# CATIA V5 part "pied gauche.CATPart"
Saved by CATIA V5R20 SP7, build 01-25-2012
Part number: pied gauche bati
Bounding box of the stored display mesh (mm): x -30.69 to -6.692, y 42.178 to 67.258, z 66.692 to 91.024
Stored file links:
  F:\Travaux\Modélisations\CFAO_2011\CFAO_2011_MMS\CFAO_2011_MMS_DONE\CFAO_2011_MMS_jboiteux\Catia\pied gauche.CATPart
  U:\finthinkmotion\stepper.CATProduct
  F:\Travaux\Modélisations\CFAO_2011\CFAO_2011_MMS\CFAO_2011_MMS_DONE\CFAO_2011_MMS_jboiteux\Catia\bati.CATPart
  F:\Travaux\Modélisations\CFAO_2011\CFAO_2011_MMS\CFAO_2011_MMS_DONE\CFAO_2011_MMS_jboiteux\Catia\Part1.CATPart
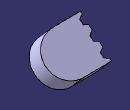
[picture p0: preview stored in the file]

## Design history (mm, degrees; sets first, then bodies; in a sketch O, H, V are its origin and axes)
Parameters
  rayontube = 9 mm {= External.royontubebati}
External parameters (linked from other documents)
  External.royontubebati = 9 mm
Set1
  DatumSurface1: linked copy from another document
  Point1: linked copy from another document
  Line1: linked copy from another document
  Line2: linked copy from another document
  DatumCurve1: linked copy from another document
Body1 (main body)
  Sketch1 on face of DatumSurface1, origin (0, 61.6478, 69.3538), H (-1, 0, 0), V (0, -0.7474, 0.6644)
    arc A1 centre (17.69, 11.4935) radius 11 from (17.69, 22.4935) to (17.69, 0.4935) ccw
    point P1 (17.69, 11.4935)
    point P2 (17.69, 22.4935)
    point P3 (17.69, 0.4935)
    reference projected point E1 (17.69, 11.4935) from Point1
    reference projected line E2 (17.69, 67.1007) -> (17.69, 13.2873) from Line1
    reference projected line E3 (17.69, 29.4313) -> (17.69, -42.32) from Line2
    point P4 (17.69, 22.4935)
    line L1 (17.69, 22.4935) -> (30.69, 22.4935)
    point P5 (30.69, 22.4935)
    point P6 (30.69, 22.4935)
    line L2 (30.69, 22.4935) -> (30.69, 21.2713)
    line L3 (30.69, 21.2713) -> (28.69, 20.049)
    point P8 (28.69, 20.049)
    line L4 (28.69, 20.049) -> (28.69, 17.6046)
    line L5 (28.69, 17.6046) -> (30.69, 16.7157)
    point P10 (30.69, 16.7157)
    line L6 (30.69, 16.7157) -> (30.69, 14.2713)
    line L7 (30.69, 14.2713) -> (28.69, 12.7157)
    line L8 (28.69, 12.7157) -> (28.69, 10.2713)
    point P13 (28.69, 10.2713)
    line L9 (28.69, 10.2713) -> (30.69, 9.049)
    point P14 (30.69, 9.049)
    line L10 (30.69, 9.049) -> (30.69, 6.6046)
    point P15 (30.69, 6.6046)
    line L11 (30.69, 6.6046) -> (28.69, 5.3824)
    point P16 (28.69, 5.3824)
    line L12 (28.69, 5.3824) -> (28.69, 2.9379)
    point P17 (28.69, 2.9379)
    line L13 (28.69, 2.9379) -> (30.69, 1.7157)
    line L14 (30.69, 1.7157) -> (30.69, 0.4935)
    line L15 (30.69, 0.4935) -> (17.69, 0.4935)
    point P20 (17.69, 0.4935)
    reference projected point E4 (17.69, 11.4935) from Point1
    projected circle E5 centre (17.69, 11.4935) radius 7 from edge of DatumCurve1
    radius A1 = 11 {= rayontube +2mm}
    length L2 = 1.2222 {= (rayontube +2mm)/9}
    length L4 = 2.4444 {= (rayontube +2mm)/4.5}
    length L6 = 2.4444 {= (rayontube+2mm)/4.5}
    length L8 = 2.4444 {= (rayontube+2mm)/4.5}
    length L10 = 2.4444 {= (rayontube+2mm)/4.5}
    length L12 = 2.4444 {= (rayontube+2mm)/4.5}
    length L14 = 1.2222 {= (rayontube+2mm)/9}
    distance P17 L15 = 2.4444 {= (rayontube+2mm)*4/18}
    distance P15 L15 = 6.1111 {= (rayontube+2mm)*10/18}
    distance P13 L15 = 9.7778 {= (rayontube+2mm)*16/18}
    distance L4 L2 = 2
    distance L8 E4 = 11 {= rayontube +2mm}
    distance L8 L10 = 2
    distance L12 L14 = 2
    distance P8 L1 = 2.4444 {= (rayontube+2mm)/4.5}
    coincidence: E1 P1, E2 P2, E3 P3, P4 A1, P10 L2, L5 P2, P14 L6, P16 L8, P20 P3, P6 P5, P2 P4
    tangency: L1 A1
    vertical: L2 V, L6 V, L10 V, L14 V
    horizontal: L15 H
  Pad1: profile Sketch1, direction (0, -0.6644, -0.7474), length 4
  Sketch2 on start face of Pad1, origin (0, 61.6478, 69.3538), H (-1, 0, 0), V (0, -0.7474, 0.6644)
    projected arc E1 centre (17.69, 11.4935) radius 11 from (17.69, 22.4935) to (17.69, 0.4935) ccw from edge [face of Pad1 from Sketch1.A1 | start face of Pad1]
    projected line E2 (17.69, 0.4935) -> (30.69, 0.4935) from edge [face of Pad1 from Sketch1.L15 | start face of Pad1]
    projected line E3 (30.69, 0.4935) -> (30.69, 1.7157) from edge [face of Pad1 from Sketch1.L14 | start face of Pad1]
    projected line E4 (30.69, 1.7157) -> (28.69, 2.9379) from edge [face of Pad1 from Sketch1.L13 | start face of Pad1]
    projected line E5 (28.69, 2.9379) -> (28.69, 5.3824) from edge [face of Pad1 from Sketch1.L12 | start face of Pad1]
    projected line E6 (28.69, 5.3824) -> (30.69, 6.6046) from edge [face of Pad1 from Sketch1.L11 | start face of Pad1]
    projected line E7 (30.69, 6.6046) -> (30.69, 9.049) from edge [face of Pad1 from Sketch1.L10 | start face of Pad1]
    projected line E8 (30.69, 9.049) -> (28.69, 10.2713) from edge [face of Pad1 from Sketch1.L9 | start face of Pad1]
    projected line E9 (28.69, 10.2713) -> (28.69, 12.7157) from edge [face of Pad1 from Sketch1.L8 | start face of Pad1]
    projected line E10 (28.69, 12.7157) -> (30.69, 14.2713) from edge [face of Pad1 from Sketch1.L7 | start face of Pad1]
    projected line E11 (30.69, 14.2713) -> (30.69, 16.7157) from edge [face of Pad1 from Sketch1.L6 | start face of Pad1]
    projected line E12 (30.69, 16.7157) -> (28.69, 17.6046) from edge [face of Pad1 from Sketch1.L5 | start face of Pad1]
    projected line E13 (28.69, 17.6046) -> (28.69, 20.049) from edge [face of Pad1 from Sketch1.L4 | start face of Pad1]
    projected line E14 (28.69, 20.049) -> (30.69, 21.2713) from edge [face of Pad1 from Sketch1.L3 | start face of Pad1]
    projected line E15 (30.69, 21.2713) -> (30.69, 22.4935) from edge [face of Pad1 from Sketch1.L2 | start face of Pad1]
    projected line E16 (30.69, 22.4935) -> (17.69, 22.4935) from edge [face of Pad1 from Sketch1.L1 | start face of Pad1]
  Pad2: profile Sketch2, direction (0, 0.6644, 0.7474), length 9 {= rayontube}
  Point2: type OnCurve, Support edge [face of Pad2 | end face of Pad2], Ratio 1
  Point3: type OnCurve, Support edge [face of Pad2 | end face of Pad2], Ratio 0
  Line3: type PtPt, FirstPoint Point2, SecondPoint Point3
  Plane1: type Offset, RefPlane end face of Pad2, Offset 0, reversed
  Plane2: type Angle, RefPlane Plane1, Direction Line3, Angle -10
  Split1: SplitPlane Plane2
